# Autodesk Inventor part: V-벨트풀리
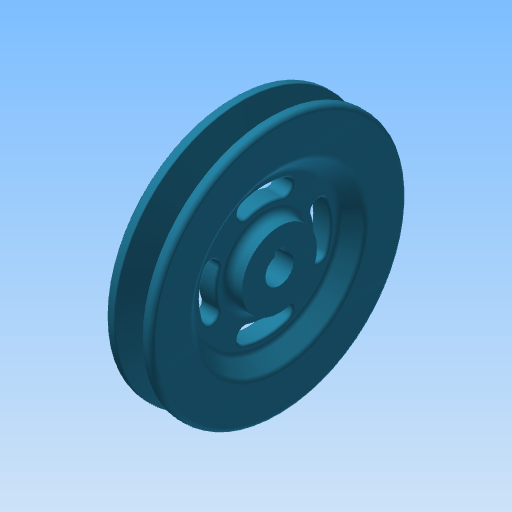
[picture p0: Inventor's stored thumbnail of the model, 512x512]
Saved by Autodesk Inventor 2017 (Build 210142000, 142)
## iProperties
Created: 2015-12
Part Number: V-벨트풀리
Document SubType Name: Modeling
Designer: mdu
Density: 8.08 g/cm^3
Material: 스테인리스강
Mass: 919.298 g
Surface Area: 326.109 cm^2
Volume: 113.774 cm^3
Appearance: 터키옥색
Author: mdu
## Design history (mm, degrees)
sketch "스케치1"
  geometry: L1 (-10, 0)-(10, 0); L2 (-10, 0)-(-10, 16); L3 (-10, 16)-(-4, 16); L4 (-4, 16)-(-4, 31); L5 (-4, 31)-(-10, 37); L6 (-10, 37)-(-10, 54.5); L7 (-10, 54.5)-(-5.976, 54.5); L8 (-5.976, 54.5)-(-2.154, 42); L9 (-2.154, 42)-(2.154, 42); L10 (2.154, 42)-(5.976, 54.5); L11 (5.976, 54.5)-(10, 54.5); L12 (10, 54.5)-(10, 37); L13 (10, 37)-(4, 31); L14 (4, 31)-(4, 16); L15 (4, 16)-(10, 16); L16 (10, 16)-(10, 0); L17 (-4.6, 50)-(4.6, 50); 2 further points
  constraints: 34 end point, 7 parallel, 6 equal length, 5 collinear, 3 perpendicular, 2 point on line, 1 coincident, 1 horizontal, 1 midpoint
  dimensions: "d0" = 20 distance of L1.start L1.end; "d1" = 9.2 distance of L17.start L17.end; "d2" = 34 deg angle of L10 L8; "d3" = 4.5 distance between parallel lines of L7 L17; "d4" = 8 distance between parallel lines of L9 L17; "d6" = 100 diameter of L17 L1; "d7" = 32 diameter of L3 L1; "d8" = 74 diameter of L5.end L1; "d9" = 6 distance of L2.end L3.end; "d10" = 135 deg angle of L4 L5
revolve "회전1" sketch "스케치1" stored, may be unused: angle "d11" = 90 deg
fillet "모깎기1" dims "d12" = 2, "d13" = 0.5, "d14" = 1, "d15" = 3
sketch "스케치2"
  geometry: L1 (-2, 5.657)-(-2, 7.8); L2 (-2, 7.8)-(2, 7.8); L3 (2, 7.8)-(2, 5.657); A1 r 6 centre (0, 0) between (-2, 5.657) and (2, 5.657); 1 further point
  constraints: 6 end point, 2 parallel, 2 point on circle, 1 centre point, 1 coincident, 1 perpendicular, 1 vertical
  dimensions: "d16" = 12 diameter of A1; "d17" = 4 distance of L1.end L2.end; "d18" = 13.8 dimension on A1 L2 (computed from d16)
extrude "돌출1" cut sketch "스케치2" stored distance "d19" = 10; taper "d20" = 0 deg
sketch "스케치3"
  geometry: L1 (0, 0)-(0, 24.5); L2 (0, 0)-(-8.379, 23.022); C1 r 29.757 at (0, 0) reference; C2 r 19 at (0, 0) reference; A1 r 24.5 centre (0, 0) between (0, 24.5) and (-8.379, 23.022); A2 r 3.3 centre (-8.379, 23.022) between (-9.508, 26.123) and (-7.251, 19.921); A3 r 3.3 centre (8.379, 23.022) between (7.251, 19.921) and (9.508, 26.123); A4 r 27.8 centre (0, 0) between (9.508, 26.123) and (-9.508, 26.123); A5 r 21.2 centre (0, 0) between (7.251, 19.921) and (-7.251, 19.921); 1 further point
  constraints: 10 point on circle, 5 centre point, 4 coincident, 4 end point, 1 point on line, 1 symmetric about line, 1 tangent, 1 vertical, 1 other
  dimensions: "d24" = 49 diameter of A1; "d27" = 20 deg angle of L1 L2; "d29" = 6.6 diameter of A2
extrude "돌출2" cut sketch "스케치3" stored distance "d30" = 10; taper "d31" = 0 deg
fillet "모깎기2" dims "d32" = 1
node "솔리드1"
pattern_circular "원형 패턴1" dims angle "d34" = 360 deg
